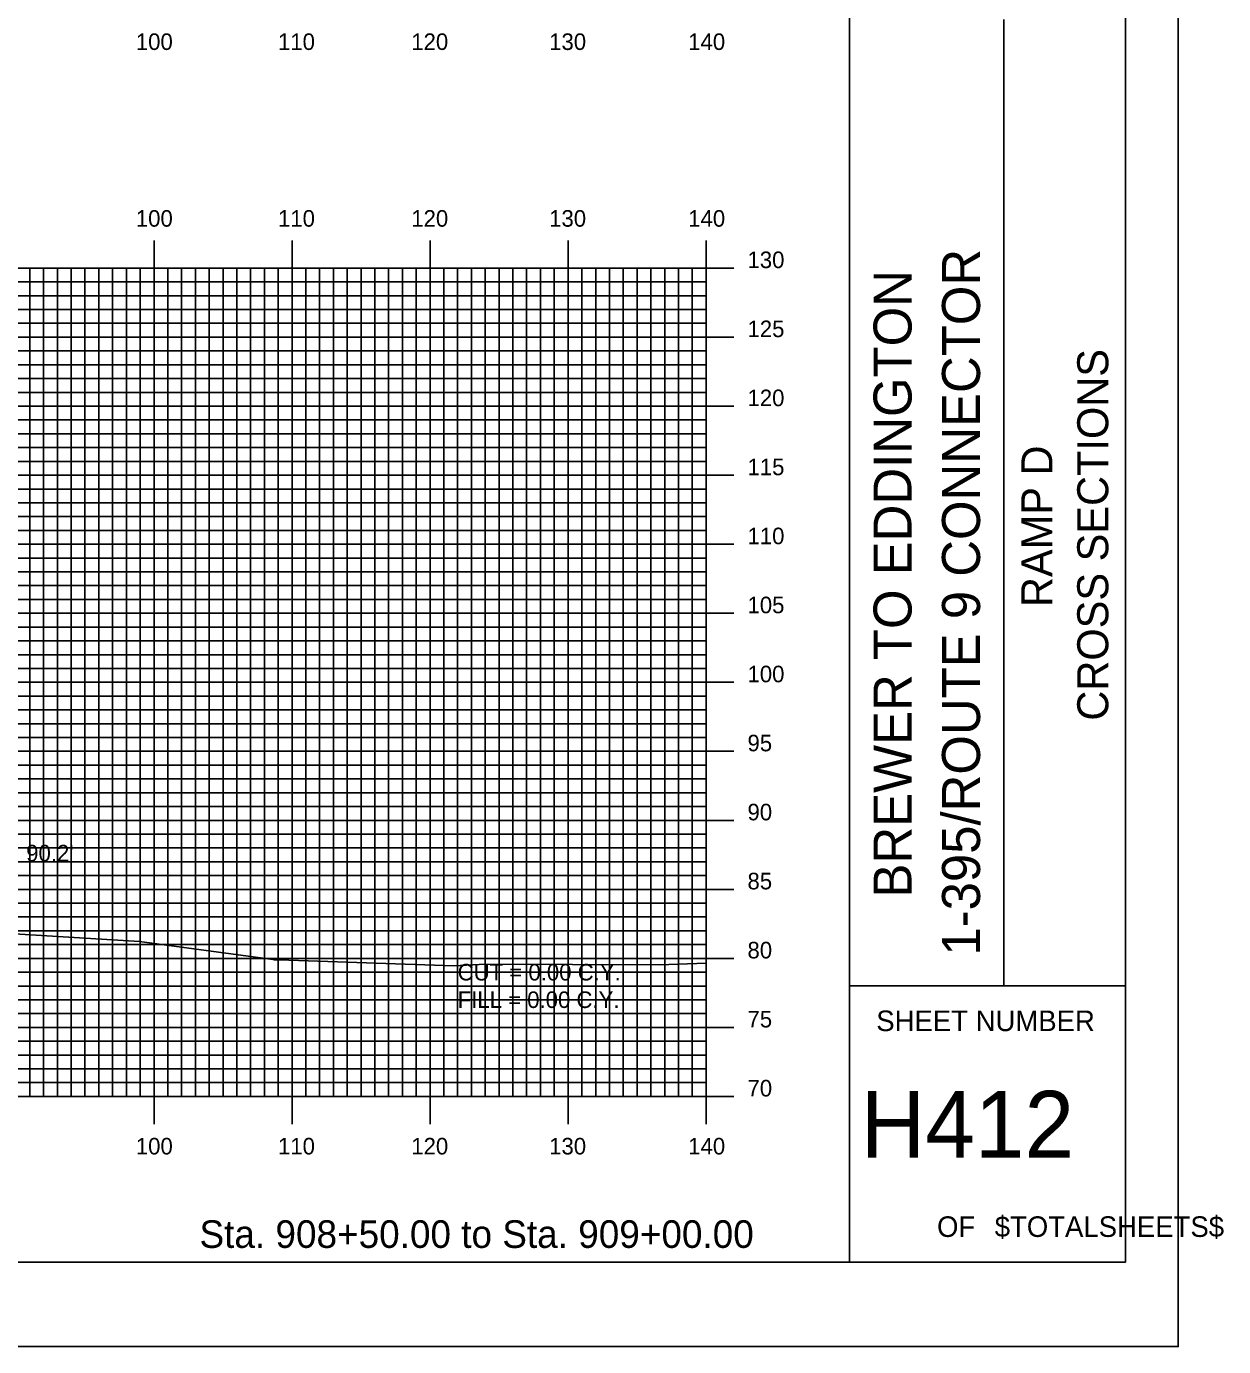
# Model space of a CAD drawing. Extents: x 858684 to 859027, y 364765 to 364985.
# Drawn here: x 858940.6 to 859027.3, y 364765.2 to 364860.8 of the extents above; entities that cross this region are included whole.
import ezdxf

# ---------------------------------------------------------------- set-up
doc = ezdxf.new("R2010")
doc.units = 0
for name, color, linetype in [('BORDER', 7, 'Continuous'), ('D_Text_Standard', 7, 'Continuous'), ('H_V ANNOTATION', 7, 'Continuous'), ('MAJOR', 7, 'Continuous'), ('MINOR', 7, 'Continuous'), ('PLOT BOUNDARY', 7, 'Continuous'), ('S_Roadway_Centerline', 7, 'Continuous')]:
    doc.layers.add(name, color=color, linetype=linetype)

msp = doc.modelspace()

# ---------------------------------------------------------------- linework, layer by layer
at = {"layer": 'BORDER'}
for p, q in [((859000.247, 364771.302), (859000.247, 364981.302)), ((859011.429, 364791.308), (859011.429, 364861.308)), ((859000.247, 364791.308), (859020.247, 364791.308))]:
    msp.add_line(p, q, dxfattribs=at)
msp.add_lwpolyline([(858700.247, 364771.302), (859020.247, 364771.302), (859020.247, 364981.302), (858700.247, 364981.302)], close=True, dxfattribs=at)
at = {"layer": 'MAJOR'}
for p, q in [((858949.847, 364845.306), (858949.847, 364843.302)), ((858959.847, 364845.306), (858959.847, 364843.302)), ((858969.847, 364845.306), (858969.847, 364843.302)), ((858979.847, 364845.306), (858979.847, 364843.302)), ((858989.847, 364845.306), (858989.847, 364843.302)), ((858709.847, 364843.302), (858989.847, 364843.302)), ((858709.847, 364843.302), (858989.847, 364843.302)), ((858949.847, 364783.302), (858949.847, 364843.302)), ((858959.847, 364783.302), (858959.847, 364843.302)), ((858969.847, 364783.302), (858969.847, 364843.302)), ((858979.847, 364783.302), (858979.847, 364843.302)), ((858991.851, 364843.302), (858987.843, 364843.302)), ((858989.847, 364783.302), (858989.847, 364843.302)), ((858989.847, 364783.302), (858989.847, 364843.302)), ((858709.847, 364838.302), (858989.847, 364838.302)), ((858991.851, 364838.302), (858987.843, 364838.302)), ((858709.847, 364833.302), (858989.847, 364833.302)), ((858991.851, 364833.302), (858987.843, 364833.302)), ((858709.847, 364828.302), (858989.847, 364828.302)), ((858991.851, 364828.302), (858987.843, 364828.302)), ((858709.847, 364823.302), (858989.847, 364823.302)), ((858991.851, 364823.302), (858987.843, 364823.302)), ((858709.847, 364818.302), (858989.847, 364818.302)), ((858991.851, 364818.302), (858987.843, 364818.302)), ((858709.847, 364813.302), (858989.847, 364813.302)), ((858991.851, 364813.302), (858987.843, 364813.302)), ((858709.847, 364808.302), (858989.847, 364808.302)), ((858991.851, 364808.302), (858987.843, 364808.302)), ((858709.847, 364803.302), (858989.847, 364803.302)), ((858991.851, 364803.302), (858987.843, 364803.302)), ((858709.847, 364798.302), (858989.847, 364798.302)), ((858991.851, 364798.302), (858987.843, 364798.302)), ((858709.847, 364793.302), (858989.847, 364793.302)), ((858991.851, 364793.302), (858987.843, 364793.302)), ((858709.847, 364788.302), (858989.847, 364788.302)), ((858991.851, 364788.302), (858987.843, 364788.302)), ((858709.847, 364783.302), (858989.847, 364783.302)), ((858709.847, 364783.302), (858989.847, 364783.302)), ((858949.847, 364781.298), (858949.847, 364783.302)), ((858959.847, 364781.298), (858959.847, 364783.302)), ((858969.847, 364781.298), (858969.847, 364783.302)), ((858979.847, 364781.298), (858979.847, 364783.302)), ((858991.851, 364783.302), (858987.843, 364783.302)), ((858989.847, 364781.298), (858989.847, 364783.302))]:
    msp.add_line(p, q, dxfattribs=at)
at = {"layer": 'MINOR'}
for p, q in [((858940.847, 364783.302), (858940.847, 364843.302)), ((858941.847, 364783.302), (858941.847, 364843.302)), ((858942.847, 364783.302), (858942.847, 364843.302)), ((858943.847, 364783.302), (858943.847, 364843.302)), ((858944.847, 364783.302), (858944.847, 364843.302)), ((858945.847, 364783.302), (858945.847, 364843.302)), ((858946.847, 364783.302), (858946.847, 364843.302)), ((858947.847, 364783.302), (858947.847, 364843.302)), ((858948.847, 364783.302), (858948.847, 364843.302)), ((858950.847, 364783.302), (858950.847, 364843.302)), ((858951.847, 364783.302), (858951.847, 364843.302)), ((858952.847, 364783.302), (858952.847, 364843.302)), ((858953.847, 364783.302), (858953.847, 364843.302)), ((858954.847, 364783.302), (858954.847, 364843.302)), ((858955.847, 364783.302), (858955.847, 364843.302)), ((858956.847, 364783.302), (858956.847, 364843.302)), ((858957.847, 364783.302), (858957.847, 364843.302)), ((858958.847, 364783.302), (858958.847, 364843.302)), ((858960.847, 364783.302), (858960.847, 364843.302)), ((858961.847, 364783.302), (858961.847, 364843.302)), ((858962.847, 364783.302), (858962.847, 364843.302)), ((858963.847, 364783.302), (858963.847, 364843.302)), ((858964.847, 364783.302), (858964.847, 364843.302)), ((858965.847, 364783.302), (858965.847, 364843.302)), ((858966.847, 364783.302), (858966.847, 364843.302)), ((858967.847, 364783.302), (858967.847, 364843.302)), ((858968.847, 364783.302), (858968.847, 364843.302)), ((858970.847, 364783.302), (858970.847, 364843.302)), ((858971.847, 364783.302), (858971.847, 364843.302)), ((858972.847, 364783.302), (858972.847, 364843.302)), ((858973.847, 364783.302), (858973.847, 364843.302)), ((858974.847, 364783.302), (858974.847, 364843.302)), ((858975.847, 364783.302), (858975.847, 364843.302)), ((858976.847, 364783.302), (858976.847, 364843.302)), ((858977.847, 364783.302), (858977.847, 364843.302)), ((858978.847, 364783.302), (858978.847, 364843.302)), ((858980.847, 364783.302), (858980.847, 364843.302)), ((858981.847, 364783.302), (858981.847, 364843.302)), ((858982.847, 364783.302), (858982.847, 364843.302)), ((858983.847, 364783.302), (858983.847, 364843.302)), ((858984.847, 364783.302), (858984.847, 364843.302)), ((858985.847, 364783.302), (858985.847, 364843.302)), ((858986.847, 364783.302), (858986.847, 364843.302)), ((858987.847, 364783.302), (858987.847, 364843.302)), ((858988.847, 364783.302), (858988.847, 364843.302)), ((858709.847, 364842.302), (858989.847, 364842.302)), ((858989.847, 364842.302), (858987.843, 364842.302)), ((858709.847, 364841.302), (858989.847, 364841.302)), ((858989.847, 364841.302), (858987.843, 364841.302)), ((858709.847, 364840.302), (858989.847, 364840.302)), ((858989.847, 364840.302), (858987.843, 364840.302)), ((858709.847, 364839.302), (858989.847, 364839.302)), ((858989.847, 364839.302), (858987.843, 364839.302)), ((858709.847, 364837.302), (858989.847, 364837.302)), ((858989.847, 364837.302), (858987.843, 364837.302)), ((858709.847, 364836.302), (858989.847, 364836.302)), ((858989.847, 364836.302), (858987.843, 364836.302)), ((858709.847, 364835.302), (858989.847, 364835.302)), ((858989.847, 364835.302), (858987.843, 364835.302)), ((858709.847, 364834.302), (858989.847, 364834.302)), ((858989.847, 364834.302), (858987.843, 364834.302)), ((858709.847, 364832.302), (858989.847, 364832.302)), ((858989.847, 364832.302), (858987.843, 364832.302)), ((858709.847, 364831.302), (858989.847, 364831.302)), ((858989.847, 364831.302), (858987.843, 364831.302)), ((858709.847, 364830.302), (858989.847, 364830.302)), ((858989.847, 364830.302), (858987.843, 364830.302)), ((858709.847, 364829.302), (858989.847, 364829.302)), ((858989.847, 364829.302), (858987.843, 364829.302)), ((858709.847, 364827.302), (858989.847, 364827.302)), ((858989.847, 364827.302), (858987.843, 364827.302)), ((858709.847, 364826.302), (858989.847, 364826.302)), ((858989.847, 364826.302), (858987.843, 364826.302)), ((858709.847, 364825.302), (858989.847, 364825.302)), ((858989.847, 364825.302), (858987.843, 364825.302)), ((858709.847, 364824.302), (858989.847, 364824.302)), ((858989.847, 364824.302), (858987.843, 364824.302)), ((858709.847, 364822.302), (858989.847, 364822.302)), ((858989.847, 364822.302), (858987.843, 364822.302)), ((858709.847, 364821.302), (858989.847, 364821.302)), ((858989.847, 364821.302), (858987.843, 364821.302)), ((858709.847, 364820.302), (858989.847, 364820.302)), ((858989.847, 364820.302), (858987.843, 364820.302)), ((858709.847, 364819.302), (858989.847, 364819.302)), ((858989.847, 364819.302), (858987.843, 364819.302)), ((858709.847, 364817.302), (858989.847, 364817.302)), ((858989.847, 364817.302), (858987.843, 364817.302)), ((858709.847, 364816.302), (858989.847, 364816.302)), ((858989.847, 364816.302), (858987.843, 364816.302)), ((858709.847, 364815.302), (858989.847, 364815.302)), ((858989.847, 364815.302), (858987.843, 364815.302)), ((858709.847, 364814.302), (858989.847, 364814.302)), ((858989.847, 364814.302), (858987.843, 364814.302)), ((858709.847, 364812.302), (858989.847, 364812.302)), ((858989.847, 364812.302), (858987.843, 364812.302)), ((858709.847, 364811.302), (858989.847, 364811.302)), ((858989.847, 364811.302), (858987.843, 364811.302)), ((858709.847, 364810.302), (858989.847, 364810.302)), ((858989.847, 364810.302), (858987.843, 364810.302)), ((858709.847, 364809.302), (858989.847, 364809.302)), ((858989.847, 364809.302), (858987.843, 364809.302)), ((858709.847, 364807.302), (858989.847, 364807.302)), ((858989.847, 364807.302), (858987.843, 364807.302)), ((858709.847, 364806.302), (858989.847, 364806.302)), ((858989.847, 364806.302), (858987.843, 364806.302)), ((858709.847, 364805.302), (858989.847, 364805.302)), ((858989.847, 364805.302), (858987.843, 364805.302)), ((858709.847, 364804.302), (858989.847, 364804.302)), ((858989.847, 364804.302), (858987.843, 364804.302)), ((858709.847, 364802.302), (858989.847, 364802.302)), ((858989.847, 364802.302), (858987.843, 364802.302)), ((858709.847, 364801.302), (858989.847, 364801.302)), ((858989.847, 364801.302), (858987.843, 364801.302)), ((858709.847, 364800.302), (858989.847, 364800.302)), ((858989.847, 364800.302), (858987.843, 364800.302)), ((858709.847, 364799.302), (858989.847, 364799.302)), ((858989.847, 364799.302), (858987.843, 364799.302)), ((858709.847, 364797.302), (858989.847, 364797.302)), ((858989.847, 364797.302), (858987.843, 364797.302)), ((858709.847, 364796.302), (858989.847, 364796.302)), ((858989.847, 364796.302), (858987.843, 364796.302)), ((858709.847, 364795.302), (858989.847, 364795.302)), ((858989.847, 364795.302), (858987.843, 364795.302)), ((858709.847, 364794.302), (858989.847, 364794.302)), ((858989.847, 364794.302), (858987.843, 364794.302)), ((858709.847, 364792.302), (858989.847, 364792.302)), ((858989.847, 364792.302), (858987.843, 364792.302)), ((858709.847, 364791.302), (858989.847, 364791.302)), ((858989.847, 364791.302), (858987.843, 364791.302)), ((858709.847, 364790.302), (858989.847, 364790.302)), ((858989.847, 364790.302), (858987.843, 364790.302)), ((858709.847, 364789.302), (858989.847, 364789.302)), ((858989.847, 364789.302), (858987.843, 364789.302)), ((858709.847, 364787.302), (858989.847, 364787.302)), ((858989.847, 364787.302), (858987.843, 364787.302)), ((858709.847, 364786.302), (858989.847, 364786.302)), ((858989.847, 364786.302), (858987.843, 364786.302)), ((858709.847, 364785.302), (858989.847, 364785.302)), ((858989.847, 364785.302), (858987.843, 364785.302)), ((858709.847, 364784.302), (858989.847, 364784.302)), ((858989.847, 364784.302), (858987.843, 364784.302))]:
    msp.add_line(p, q, dxfattribs=at)
at = {"layer": 'PLOT BOUNDARY'}
msp.add_lwpolyline([(858684.06, 364765.184), (859024.06, 364765.184), (859024.06, 364985.184), (858684.06, 364985.184)], close=True, dxfattribs=at)
at = {"layer": 'S_Roadway_Centerline'}
msp.add_lwpolyline([(858931.026, 364795.608), (858948.808, 364794.518), (858958.447, 364793.214), (858958.564, 364793.204), (858958.927, 364793.198), (858971.562, 364792.758), (858973.857, 364792.878), (858986.478, 364792.834), (858989.847, 364792.956)], dxfattribs=at)

# ---------------------------------------------------------------- texts
at = {"layer": 'BORDER'}
for s, height, p in [('1-395/ROUTE 9 CONNECTOR', 2.75575, (859009.696, 364793.502)), ('BREWER TO EDDINGTON', 2.75575, (859004.736, 364797.711)), ('CROSS SECTIONS', 2.25, (859018.988, 364810.524)), ('RAMP D', 2.25, (859014.938, 364818.752))]:
    msp.add_text(s, height=height, rotation=90, dxfattribs=at).set_placement(p)
for s, height, p in [('SHEET NUMBER', 1.49054, (859002.178, 364788.035)), ('H412', 4.8388, (859001.049, 364778.867)), ('OF', 1.4905, (859006.581, 364773.128)), ('$TOTALSHEETS$', 1.49054, (859010.76, 364773.128))]:
    msp.add_text(s, height=height, dxfattribs=at).set_placement(p)
at = {"layer": 'D_Text_Standard'}
for s, p in [("90.2'", (858940.586, 364800.326)), ('CUT = 0.00 C.Y.', (858971.847, 364791.702)), ('FILL = 0.00 C.Y.', (858971.847, 364789.71))]:
    msp.add_text(s, height=1.2, dxfattribs=at).set_placement(p)
at = {"layer": 'H_V ANNOTATION'}
for s, height, p in [('100', 1.2, (858948.53, 364859.102)), ('110', 1.2, (858958.83, 364859.102)), ('120', 1.2, (858968.487, 364859.102)), ('130', 1.2, (858978.477, 364859.102)), ('140', 1.2, (858988.552, 364859.102)), ('100', 1.2, (858948.53, 364846.302)), ('110', 1.2, (858958.83, 364846.302)), ('120', 1.2, (858968.487, 364846.302)), ('130', 1.2, (858978.477, 364846.302)), ('140', 1.2, (858988.552, 364846.302)), ('130', 1.2, (858992.847, 364843.302)), ('125', 1.2, (858992.847, 364838.302)), ('120', 1.2, (858992.847, 364833.302)), ('115', 1.2, (858992.847, 364828.302)), ('110', 1.2, (858992.847, 364823.302)), ('105', 1.2, (858992.847, 364818.302)), ('100', 1.2, (858992.847, 364813.302)), ('95', 1.2, (858992.847, 364808.302)), ('90', 1.2, (858992.847, 364803.302)), ('85', 1.2, (858992.847, 364798.302)), ('80', 1.2, (858992.847, 364793.302)), ('75', 1.2, (858992.847, 364788.302)), ('70', 1.2, (858992.847, 364783.302)), ('100', 1.2, (858948.53, 364779.102)), ('110', 1.2, (858958.83, 364779.102)), ('120', 1.2, (858968.487, 364779.102)), ('130', 1.2, (858978.477, 364779.102)), ('140', 1.2, (858988.552, 364779.102)), ('Sta. 908+50.00 to Sta. 909+00.00', 2.0004, (858953.144, 364772.332))]:
    msp.add_text(s, height=height, dxfattribs=at).set_placement(p)

doc.saveas('drawing.dxf')
